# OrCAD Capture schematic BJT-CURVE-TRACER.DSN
size A; title: BJT Curve Tracer
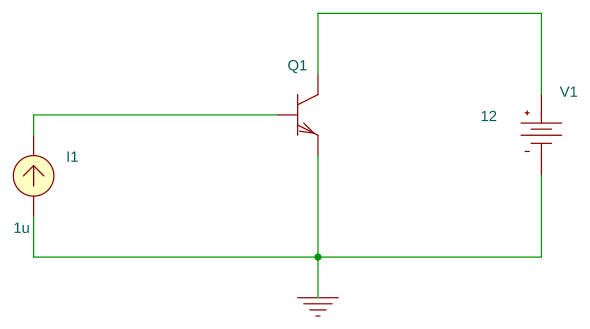
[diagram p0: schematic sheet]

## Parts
I1  IDC
Q1  QbreakN
V1  VDC

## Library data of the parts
I1 = IDC: DC: 1u
Q1 = QbreakN
V1 = VDC: DC: 12

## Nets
0: I1.1(+) Q1.2(e) V1.1(-)
N00071: I1.2(-) Q1.0(b)
N00103: Q1.1(c) V1.0(+)
